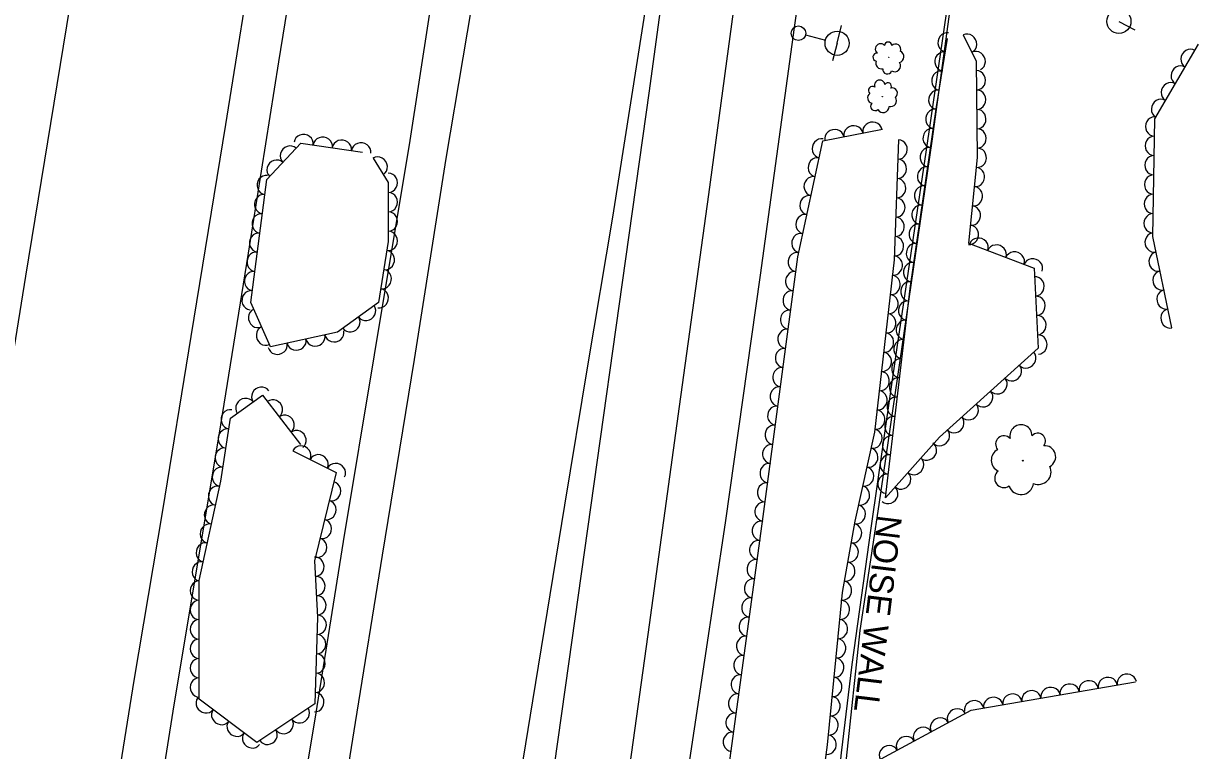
# Model space of a CAD drawing. Extents: x 1722896 to 1754269, y 648279 to 666297.
# Drawn here: x 1725704.7 to 1725947.4, y 660025.8 to 660175.9 of the extents above; entities that cross this region are included whole.
import ezdxf

# ---------------------------------------------------------------- set-up
doc = ezdxf.new("R2010")
doc.units = 0
for name, color, linetype in [('DESIGN - SCRATCH - User 1', 7, 'Continuous'), ('SURVEY - CENTERLINE - Preliminary Text', 7, 'Continuous'), ('SURVEY - DTM - Breaklines', 7, 'Continuous'), ('SURVEY - VEGETATION - Features with Text', 7, 'Continuous')]:
    doc.layers.add(name, color=color, linetype=linetype)

msp = doc.modelspace()

# ---------------------------------------------------------------- linework, layer by layer
at = {"layer": 'DESIGN - SCRATCH - User 1'}
for points in [[(1725917.81, 660330.98), (1725913.82, 660302.94), (1725909.26, 660270.56), (1725906.54, 660252.79), (1725903.03, 660227.26), (1725899.57, 660202.92), (1725895.84, 660177.26), (1725892.3, 660151.6), (1725881.39, 660076.58), (1725877.4, 660050.54), (1725874.63, 660024.09), (1725869.22, 659972.54), (1725864.03, 659936.34), (1725858.72, 659891.93), (1725851.7, 659837.21), (1725850.18, 659823.2)], [(1725916.06, 660324.54), (1725912.95, 660299.79), (1725906.06, 660253.9), (1725900.43, 660215.9), (1725896.78, 660188.35), (1725891.35, 660151.22), (1725885.07, 660109.02), (1725879.68, 660071.71), (1725875.78, 660043.54), (1725873.56, 660025.29), (1725868.35, 659974.6), (1725865.36, 659953.72), (1725861.7, 659924.19), (1725857.84, 659890.83), (1725853.71, 659858.25), (1725848.92, 659823.09), (1725848.94, 659823.25)]]:
    msp.add_lwpolyline(points, dxfattribs=at)
at = {"layer": 'SURVEY - CENTERLINE - Preliminary Text'}
for points in [[(1725855.76, 660319.02), (1725851.95, 660293.22), (1725846.98, 660265.99), (1725840.38, 660225.19), (1725833.79, 660183.22), (1725826.35, 660135.94), (1725821.16, 660105.19), (1725816.43, 660076.41), (1725809.83, 660036.05), (1725803.6, 659997.96), (1725796.66, 659955.02), (1725789.84, 659913.42), (1725783.78, 659877.48), (1725777.8, 659839.82), (1725774.69, 659822.14)], [(1725855.76, 660319.02), (1725852.16, 660290.86), (1725845.53, 660245.16), (1725840.31, 660209.08), (1725833.92, 660162.02), (1725828.35, 660122.44), (1725822.52, 660080.86), (1725817.24, 660043.64), (1725810.5, 659995.81), (1725805.03, 659955.63), (1725798.38, 659908.88), (1725791.87, 659861.85), (1725787.43, 659830.37), (1725786.09, 659820.32)], [(1725883.17, 660311.92), (1725876.15, 660261.85), (1725870.51, 660222.06), (1725863.85, 660175.12), (1725856.85, 660123.94), (1725849.6, 660072.81), (1725841.08, 660016.08), (1725832.95, 659956.79), (1725823.58, 659893.63), (1725815.74, 659820.99)], [(1725869.72, 660308.32), (1725864.97, 660274.1), (1725858.45, 660229.12), (1725852.79, 660189.63), (1725846.2, 660140.6), (1725840.11, 660096.79), (1725833.93, 660051.71), (1725827.59, 660006.09), (1725821.44, 659965.67), (1725814.68, 659915.91), (1725809.29, 659876.56), (1725804.12, 659838.94), (1725802.03, 659817.94)], [(1725816.17, 660296.26), (1725811.8, 660269.23), (1725805.34, 660227.23), (1725798.96, 660189.71), (1725791.91, 660148.05), (1725785.38, 660106.53), (1725778.75, 660066.1), (1725773.23, 660031.54), (1725766.5, 659989.84), (1725761.4, 659957.43), (1725755.47, 659921.9), (1725749.46, 659885.29), (1725743.47, 659847.94), (1725740.11, 659828.64)], [(1725807.44, 660293.84), (1725801.02, 660253.11), (1725795.27, 660218.3), (1725790.34, 660189.78), (1725784.48, 660151.72), (1725777.15, 660107.45), (1725770.73, 660068.93), (1725764.79, 660031.84), (1725758.19, 659992.41), (1725752.39, 659956.16), (1725744.64, 659908.67), (1725738.05, 659867.82), (1725731.88, 659831.76)], [(1725776.29, 660285.77), (1725772.32, 660261.45), (1725766.32, 660226.39), (1725763.01, 660202.83), (1725757.33, 660167.98), (1725751.12, 660128.47), (1725745.35, 660093.04), (1725735.56, 660033.92), (1725729.85, 659997.82), (1725723.75, 659959.51), (1725717.25, 659919.23), (1725710.12, 659874.02), (1725705.15, 659844.5)], [(1725767.06, 660282.88), (1725759.7, 660236.17), (1725752.81, 660195.05), (1725746.43, 660155.05), (1725739.28, 660111.26), (1725733.4, 660075.3), (1725727.48, 660040.2), (1725721.24, 660001.04), (1725715.69, 659966.6), (1725708.94, 659924.09), (1725702.3, 659883.66), (1725696.01, 659845.11)], [(1725728.96, 660271.57), (1725721.98, 660227.82), (1725714.22, 660179.22), (1725705.11, 660123.75), (1725698.78, 660084.7), (1725691.48, 660038.26), (1725682.58, 659984.77), (1725675.47, 659940.61), (1725668.65, 659896.97), (1725663.3, 659864.99), (1725662.5, 659860.28)]]:
    msp.add_lwpolyline(points, dxfattribs=at)
at = {"layer": 'SURVEY - DTM - Breaklines'}
for p, q in [((1725872.74, 660171.84), (1725873.68, 660175.47)), ((1725930.94, 660176.35), (1725934.25, 660174.6)), ((1725866.2, 660173.54), (1725870.32, 660172.47)), ((1725872.74, 660171.84), (1725871.8, 660168.21))]:
    msp.add_line(p, q, dxfattribs=at)
for centre, radius in [((1725930.94, 660176.35), 2.5), ((1725864.75, 660173.91), 1.5), ((1725872.74, 660171.84), 2.5)]:
    msp.add_circle(centre, radius, dxfattribs=at)
at = {"layer": 'SURVEY - VEGETATION - Features with Text'}
for points in [[(1725898.77, 660173.54), (1725901.48, 660168.15), (1725901.7, 660148.22), (1725899.9, 660130.52), (1725913.44, 660125.35), (1725914.27, 660108.86), (1725893.89, 660090.5), (1725882.7, 660077.92), (1725887.83, 660121.17), (1725893.28, 660158.68), (1725895.57, 660172.8)], [(1725941.9, 660113.05), (1725937.95, 660131.91), (1725938.33, 660156.22), (1725947.38, 660171.62)], [(1725825.28, 659819.19), (1725831.34, 659863.56), (1725835.57, 659910.58), (1725841.87, 659963.61), (1725848.83, 660011.07), (1725857.49, 660074.09), (1725864.62, 660127.73), (1725869.81, 660151.67), (1725882.09, 660154.08)], [(1725776.89, 660148.11), (1725780.04, 660143.1), (1725780.04, 660130.88), (1725778.03, 660118.3), (1725769.52, 660112.16), (1725755.71, 660109.14), (1725751.62, 660118.27), (1725754.95, 660143.68), (1725761.98, 660151.21), (1725774.7, 660149.36)], [(1725885.41, 660151.89), (1725884.49, 660127.07), (1725880.43, 660091.48), (1725876.39, 660073.11), (1725873.77, 660058.41), (1725870.7, 660026.93), (1725860.01, 659945.89), (1725852.75, 659876.56), (1725845.68, 659829.76), (1725846.32, 659820.58)], [(1725760.32, 660087.69), (1725769.27, 660083.15), (1725764.83, 660064.97), (1725765.42, 660053.28), (1725764.85, 660035.42), (1725752.9, 660027.41), (1725741.01, 660036.4), (1725741.01, 660060.89), (1725745.43, 660081.41), (1725747.44, 660094.42), (1725754.06, 660099.13), (1725761.88, 660088.97)], [(1725925.75, 659932.89), (1725917.6, 659941.2), (1725898.5, 659973.89), (1725883.16, 659983.83), (1725875.03, 659996.41), (1725879.28, 660022.64), (1725900.43, 660034.09), (1725934.36, 660039.98)]]:
    msp.add_lwpolyline(points, dxfattribs=at)
for centre, radius in [((1725883.41, 660168.9), 0.038), ((1725882.09, 660160.8), 0.0377), ((1725911.09, 660085.62), 0.08)]:
    msp.add_circle(centre, radius, dxfattribs=at)
for centre, radius, start, end in [((1725881.71, 660170.65), 1.09, 40.2149, 233.6346), ((1725883.29, 660171.34), 0.748, 0.1943, 178.9399), ((1725880.96, 660168.96), 0.827, 82.8336, 260.1528), ((1725884.8, 660170.57), 1.09, 338.0781, 134.867), ((1725885.28, 660169.05), 1.24, 287.1308, 64.6551), ((1725881.91, 660167.71), 1.17, 158.1207, 284.9663), ((1725884.62, 660167.17), 1.23, 238.0267, 33.8652), ((1725883.1, 660166.39), 0.909, 168.2796, 343.2798), ((1725880.03, 660162.09), 0.82, 52.0538, 229.3729), ((1725881.53, 660163.16), 1.08, 9.4351, 202.8548), ((1725883.22, 660162.94), 0.741, 329.4144, 148.16), ((1725884.12, 660161.52), 1.08, 307.2982, 104.0872), ((1725880.2, 660160.55), 1.16, 127.3408, 254.1865), ((1725883.76, 660159.98), 1.23, 256.351, 33.8752), ((1725880.55, 660158.82), 0.901, 137.4997, 312.5), ((1725882.24, 660158.72), 1.22, 207.2468, 3.0853), ((1725910.72, 660090.75), 2.29, 0.2805, 193.7002), ((1725907.22, 660089.02), 1.74, 42.8992, 220.2183), ((1725914.19, 660089.73), 1.57, 320.2598, 139.0055), ((1725907.05, 660085.72), 2.47, 118.1862, 245.0319), ((1725915.6, 660086.44), 2.29, 298.1437, 94.9326), ((1725914.31, 660083.33), 2.61, 247.1964, 24.7207), ((1725907.2, 660081.99), 1.91, 128.3452, 303.3454), ((1725910.72, 660081.2), 2.59, 198.0923, 353.9307)]:
    msp.add_arc(centre, radius, start, end, dxfattribs=at)
for centre, major_axis in [((1725895.44, 660172.02), (0.32, 1.97)), ((1725899.67, 660171.76), (0.9, -1.79)), ((1725894.8, 660168.07), (0.32, 1.97)), ((1725901.46, 660168.18), (0.9, -1.79)), ((1725945.64, 660168.65), (1.01, 1.72)), ((1725943.61, 660165.2), (1.01, 1.72)), ((1725894.16, 660164.12), (0.32, 1.97)), ((1725901.52, 660164.18), (0.02, -2)), ((1725893.52, 660160.17), (0.32, 1.97)), ((1725901.57, 660160.18), (0.02, -2)), ((1725941.58, 660161.75), (1.01, 1.72)), ((1725939.55, 660158.3), (1.01, 1.72)), ((1725892.92, 660156.22), (0.29, 1.98)), ((1725901.61, 660156.18), (0.02, -2)), ((1725876.11, 660152.91), (1.96, 0.39)), ((1725880.03, 660153.68), (1.96, 0.39)), ((1725938.3, 660154.64), (0.03, 2)), ((1725762.55, 660151.12), (1.98, -0.29)), ((1725766.51, 660150.55), (1.98, -0.29)), ((1725872.18, 660152.14), (1.96, 0.39)), ((1725892.35, 660152.26), (0.29, 1.98)), ((1725901.66, 660152.18), (0.02, -2)), ((1725938.24, 660150.64), (0.03, 2)), ((1725759.64, 660148.7), (1.36, 1.46)), ((1725770.46, 660149.97), (1.98, -0.29)), ((1725774.42, 660149.4), (1.98, -0.29)), ((1725869.47, 660150.12), (0.42, 1.95)), ((1725885.34, 660149.89), (-0.07, -2)), ((1725891.77, 660148.3), (0.29, 1.98)), ((1725901.7, 660148.19), (-0.2, -1.99)), ((1725756.91, 660145.78), (1.36, 1.46)), ((1725777.95, 660146.41), (1.07, -1.69)), ((1725868.63, 660146.21), (0.42, 1.95)), ((1725885.19, 660145.9), (-0.07, -2)), ((1725938.18, 660146.64), (0.03, 2)), ((1725891.2, 660144.34), (0.29, 1.98)), ((1725901.29, 660144.21), (-0.2, -1.99)), ((1725754.81, 660142.56), (0.26, 1.98)), ((1725780.04, 660143.02), (0, -2)), ((1725867.78, 660142.31), (0.42, 1.95)), ((1725885.04, 660141.9), (-0.07, -2)), ((1725938.11, 660142.64), (0.03, 2)), ((1725754.29, 660138.59), (0.26, 1.98)), ((1725780.04, 660139.02), (0, -2)), ((1725866.93, 660138.4), (0.42, 1.95)), ((1725890.62, 660140.39), (0.29, 1.98)), ((1725900.89, 660140.23), (-0.2, -1.99)), ((1725938.05, 660138.64), (0.03, 2)), ((1725884.89, 660137.9), (-0.07, -2)), ((1725890.05, 660136.43), (0.29, 1.98)), ((1725900.48, 660136.25), (-0.2, -1.99)), ((1725753.77, 660134.63), (0.26, 1.98)), ((1725780.04, 660135.02), (0, -2)), ((1725866.09, 660134.49), (0.42, 1.95)), ((1725884.74, 660133.91), (-0.07, -2)), ((1725937.99, 660134.64), (0.03, 2)), ((1725780.04, 660131.02), (0, -2)), ((1725889.47, 660132.47), (0.29, 1.98)), ((1725900.07, 660132.27), (-0.2, -1.99)), ((1725753.25, 660130.66), (0.26, 1.98)), ((1725865.24, 660130.58), (0.42, 1.95)), ((1725884.6, 660129.91), (-0.07, -2)), ((1725888.9, 660128.51), (0.29, 1.98)), ((1725901.99, 660129.72), (1.87, -0.71)), ((1725938.21, 660130.67), (-0.41, 1.96)), ((1725752.73, 660126.7), (0.26, 1.98)), ((1725779.43, 660127.06), (-0.32, -1.98)), ((1725864.48, 660126.65), (0.26, 1.98)), ((1725905.72, 660128.29), (1.87, -0.71)), ((1725909.46, 660126.86), (1.87, -0.71)), ((1725939.03, 660126.75), (-0.41, 1.96)), ((1725884.36, 660125.92), (-0.23, -1.99)), ((1725888.32, 660124.55), (0.29, 1.98)), ((1725913.2, 660125.44), (1.87, -0.71)), ((1725752.21, 660122.73), (0.26, 1.98)), ((1725778.8, 660123.11), (-0.32, -1.98)), ((1725863.95, 660122.69), (0.26, 1.98)), ((1725883.91, 660121.94), (-0.23, -1.99)), ((1725913.62, 660121.61), (0.1, -2)), ((1725939.85, 660122.84), (-0.41, 1.96)), ((1725751.69, 660118.76), (0.26, 1.98)), ((1725778.17, 660119.16), (-0.32, -1.98)), ((1725863.43, 660118.72), (0.26, 1.98)), ((1725887.76, 660120.59), (0.24, 1.99)), ((1725940.67, 660118.92), (-0.41, 1.96)), ((1725883.45, 660117.97), (-0.23, -1.99)), ((1725887.29, 660116.62), (0.24, 1.99)), ((1725913.83, 660117.61), (0.1, -2)), ((1725753.06, 660115.07), (-0.82, 1.83)), ((1725775.49, 660116.47), (-1.62, -1.17)), ((1725862.9, 660114.76), (0.26, 1.98)), ((1725883, 660113.99), (-0.23, -1.99)), ((1725941.49, 660115.01), (-0.41, 1.96)), ((1725772.25, 660114.13), (-1.62, -1.17)), ((1725886.82, 660112.65), (0.24, 1.99)), ((1725914.03, 660113.62), (0.1, -2)), ((1725754.69, 660111.42), (-0.82, 1.83)), ((1725764.99, 660111.17), (-1.95, -0.43)), ((1725768.9, 660112.02), (-1.95, -0.43)), ((1725862.37, 660110.79), (0.26, 1.98)), ((1725882.55, 660110.02), (-0.23, -1.99)), ((1725914.23, 660109.62), (0.1, -2)), ((1725757.18, 660109.46), (-1.95, -0.43)), ((1725761.09, 660110.32), (-1.95, -0.43)), ((1725861.85, 660106.83), (0.26, 1.98)), ((1725886.35, 660108.68), (0.24, 1.99)), ((1725882.09, 660106.05), (-0.23, -1.99)), ((1725885.88, 660104.7), (0.24, 1.99)), ((1725911.86, 660106.69), (-1.49, -1.34)), ((1725861.32, 660102.86), (0.26, 1.98)), ((1725881.64, 660102.07), (-0.23, -1.99)), ((1725908.89, 660104.02), (-1.49, -1.34)), ((1725885.41, 660100.73), (0.24, 1.99)), ((1725905.92, 660101.34), (-1.49, -1.34)), ((1725753.75, 660098.91), (1.63, 1.16)), ((1725860.79, 660098.9), (0.26, 1.98)), ((1725881.19, 660098.1), (-0.23, -1.99)), ((1725902.95, 660098.66), (-1.49, -1.34)), ((1725750.49, 660096.59), (1.63, 1.16)), ((1725756.27, 660096.26), (1.22, -1.58)), ((1725860.26, 660094.93), (0.26, 1.98)), ((1725884.93, 660096.76), (0.24, 1.99)), ((1725899.98, 660095.99), (-1.49, -1.34)), ((1725747.4, 660094.17), (0.31, 1.98)), ((1725758.71, 660093.09), (1.22, -1.58)), ((1725880.73, 660094.12), (-0.23, -1.99)), ((1725884.46, 660092.79), (0.24, 1.99)), ((1725897, 660093.31), (-1.49, -1.34)), ((1725746.79, 660090.21), (0.31, 1.98)), ((1725761.15, 660089.92), (1.22, -1.58)), ((1725859.74, 660090.97), (0.26, 1.98)), ((1725880.14, 660090.17), (-0.43, -1.95)), ((1725894.03, 660090.63), (-1.49, -1.34)), ((1725883.99, 660088.81), (0.24, 1.99)), ((1725746.17, 660086.26), (0.31, 1.98)), ((1725762.1, 660086.78), (1.78, -0.9)), ((1725765.67, 660084.97), (1.78, -0.9)), ((1725859.21, 660087), (0.26, 1.98)), ((1725879.29, 660086.27), (-0.43, -1.95)), ((1725883.52, 660084.84), (0.24, 1.99)), ((1725891.36, 660087.66), (-1.33, -1.49)), ((1725745.56, 660082.31), (0.31, 1.98)), ((1725769.24, 660083.16), (1.78, -0.9)), ((1725858.68, 660083.04), (0.26, 1.98)), ((1725888.7, 660084.67), (-1.33, -1.49)), ((1725878.43, 660082.36), (-0.43, -1.95)), ((1725883.05, 660080.87), (0.24, 1.99)), ((1725886.04, 660081.68), (-1.33, -1.49)), ((1725744.77, 660078.39), (0.42, 1.96)), ((1725768.33, 660079.29), (-0.47, -1.94)), ((1725858.15, 660079.07), (0.26, 1.98)), ((1725877.57, 660078.45), (-0.43, -1.95)), ((1725883.38, 660078.69), (-1.33, -1.49)), ((1725767.38, 660075.41), (-0.47, -1.94)), ((1725857.63, 660075.11), (0.26, 1.98)), ((1725743.93, 660074.48), (0.42, 1.96)), ((1725876.71, 660074.54), (-0.43, -1.95)), ((1725743.09, 660070.57), (0.42, 1.96)), ((1725766.43, 660071.52), (-0.47, -1.94)), ((1725857.09, 660071.14), (0.27, 1.98)), ((1725875.95, 660070.62), (-0.35, -1.97)), ((1725742.25, 660066.66), (0.42, 1.96)), ((1725765.48, 660067.64), (-0.47, -1.94)), ((1725856.54, 660067.18), (0.27, 1.98)), ((1725875.25, 660066.68), (-0.35, -1.97)), ((1725764.9, 660063.72), (0.1, -2)), ((1725856, 660063.22), (0.27, 1.98)), ((1725741.41, 660062.75), (0.42, 1.96)), ((1725874.55, 660062.74), (-0.35, -1.97)), ((1725741.01, 660058.79), (0, 2)), ((1725765.1, 660059.72), (0.1, -2)), ((1725855.45, 660059.25), (0.27, 1.98)), ((1725873.84, 660058.8), (-0.35, -1.97)), ((1725765.3, 660055.73), (0.1, -2)), ((1725741.01, 660054.79), (0, 2)), ((1725854.91, 660055.29), (0.27, 1.98)), ((1725873.42, 660054.83), (-0.19, -1.99)), ((1725765.37, 660051.73), (-0.06, -2)), ((1725854.36, 660051.33), (0.27, 1.98)), ((1725873.03, 660050.85), (-0.19, -1.99)), ((1725741.01, 660050.79), (0, 2)), ((1725741.01, 660046.79), (0, 2)), ((1725765.25, 660047.73), (-0.06, -2)), ((1725853.82, 660047.37), (0.27, 1.98)), ((1725872.65, 660046.87), (-0.19, -1.99)), ((1725765.12, 660043.73), (-0.06, -2)), ((1725741.01, 660042.79), (0, 2)), ((1725853.27, 660043.4), (0.27, 1.98)), ((1725872.26, 660042.88), (-0.19, -1.99)), ((1725741.01, 660038.79), (0, 2)), ((1725764.99, 660039.74), (-0.06, -2)), ((1725852.73, 660039.44), (0.27, 1.98)), ((1725871.87, 660038.9), (-0.19, -1.99)), ((1725928.64, 660038.99), (1.97, 0.34)), ((1725932.58, 660039.67), (1.97, 0.34)), ((1725912.88, 660036.25), (1.97, 0.34)), ((1725916.82, 660036.93), (1.97, 0.34)), ((1725920.76, 660037.62), (1.97, 0.34)), ((1725924.7, 660038.3), (1.97, 0.34)), ((1725742.3, 660035.43), (-1.6, 1.21)), ((1725764.86, 660035.74), (-0.06, -2)), ((1725852.18, 660035.48), (0.27, 1.98)), ((1725871.48, 660034.92), (-0.19, -1.99)), ((1725901.05, 660034.2), (1.97, 0.34)), ((1725904.99, 660034.88), (1.97, 0.34)), ((1725908.94, 660035.57), (1.97, 0.34)), ((1725745.49, 660033.01), (-1.6, 1.21)), ((1725761.8, 660033.37), (-1.66, -1.11)), ((1725851.64, 660031.52), (0.27, 1.98)), ((1725897.47, 660032.48), (1.76, 0.95)), ((1725748.68, 660030.6), (-1.6, 1.21)), ((1725758.47, 660031.14), (-1.66, -1.11)), ((1725871.09, 660030.94), (-0.19, -1.99)), ((1725893.95, 660030.58), (1.76, 0.95)), ((1725751.87, 660028.19), (-1.6, 1.21)), ((1725755.15, 660028.92), (-1.66, -1.11)), ((1725851.1, 660027.55), (0.27, 1.98)), ((1725870.7, 660026.96), (-0.19, -1.99)), ((1725886.92, 660026.77), (1.76, 0.95)), ((1725890.43, 660028.68), (1.76, 0.95)), ((1725883.4, 660024.87), (1.76, 0.95))]:
    msp.add_ellipse(centre, major_axis=major_axis, ratio=0.940188, start_param=0, end_param=3.141593, dxfattribs=at)

# ---------------------------------------------------------------- texts
at = {"layer": 'DESIGN - SCRATCH - User 1'}
msp.add_text('NOISE WALL', height=5, rotation=263.0233, dxfattribs=at).set_placement((1725881.18, 660074.56))

doc.saveas('drawing.dxf')
